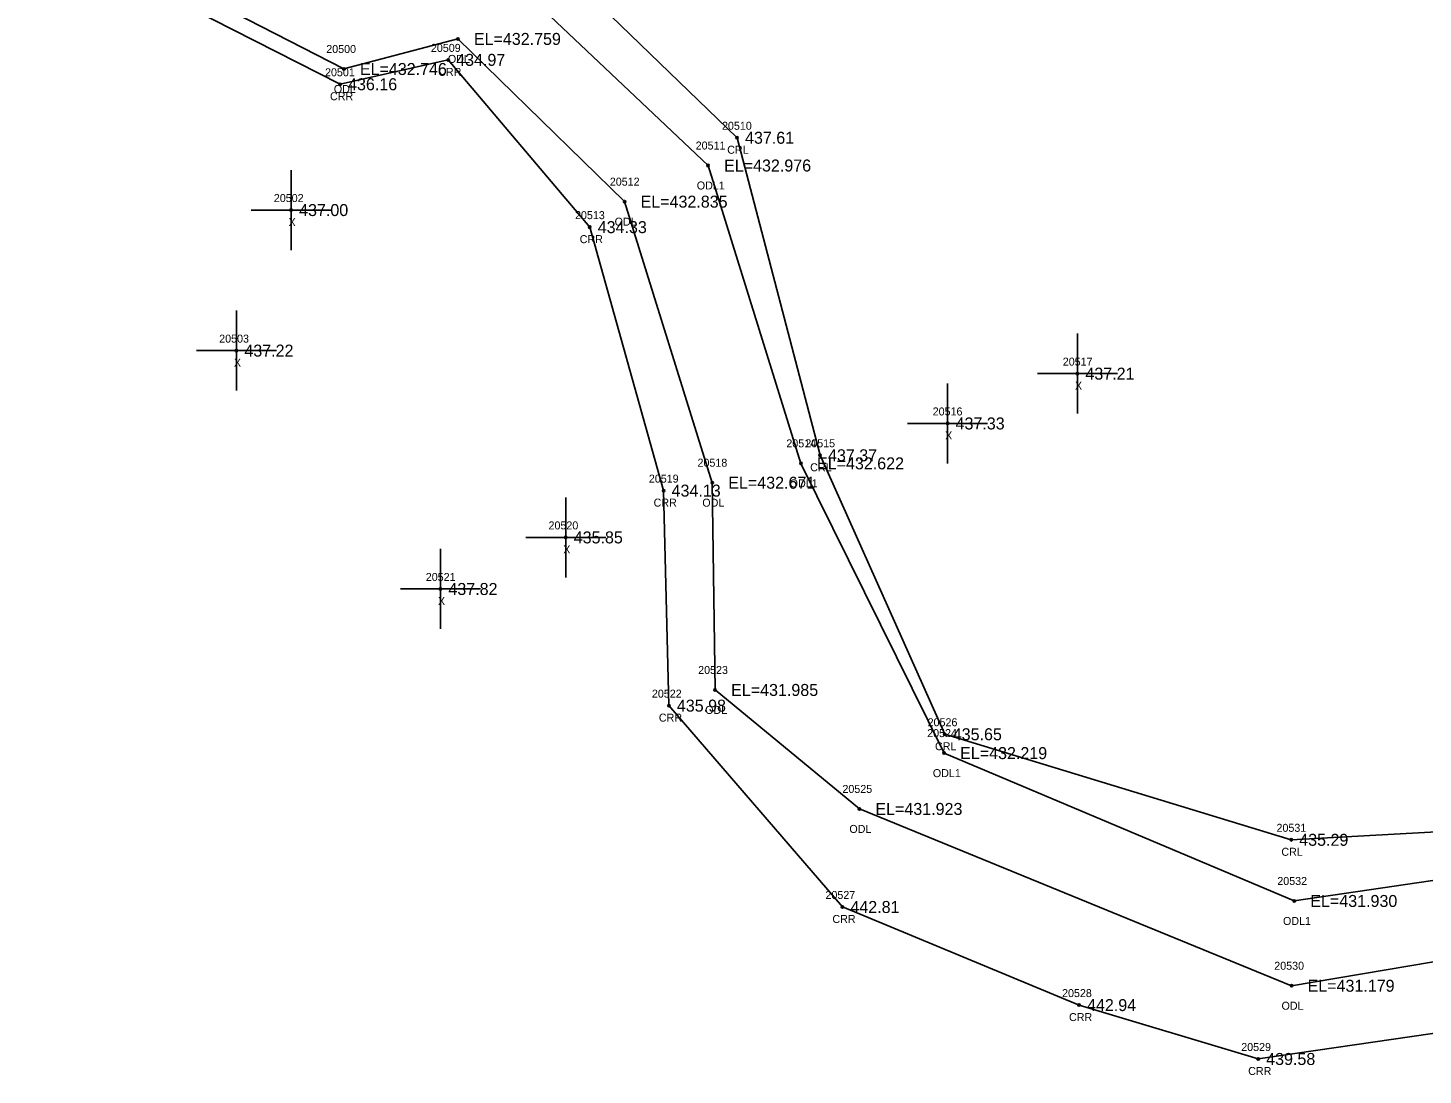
# Model space of a CAD drawing. Extents: x 1763022 to 1764007, y 824123 to 825394.
# Drawn here: x 1763608.9 to 1763783.3, y 824553.2 to 824684.2 of the extents above; entities that cross this region are included whole.
import ezdxf

# ---------------------------------------------------------------- set-up
doc = ezdxf.new("R2010")
doc.units = 0
for name, color, linetype in [('RD_EX_H2O', 7, 'Continuous'), ('RD_EX_H2O_txCode', 7, 'Continuous'), ('RD_EX_Misc', 7, 'Continuous'), ('RD_EX_Misc_txCode', 7, 'Continuous'), ('RD_EX_TX_H2O_ELEV', 7, 'Continuous'), ('RD_EX_TX_Misc_ELEV', 7, 'Continuous'), ('RD_SMD_Locator', 7, 'Continuous')]:
    doc.layers.add(name, color=color, linetype=linetype)

msp = doc.modelspace()

# ---------------------------------------------------------------- linework, layer by layer
at = {"layer": 'RD_EX_H2O'}
for points in [[(1763496.79, 824812.85), (1763505.69, 824806.42), (1763507.16, 824805.23), (1763521.58, 824789.49), (1763543.54, 824765.51), (1763572.14, 824752.09), (1763662.42, 824704.48), (1763697.56, 824670.47), (1763707.93, 824630.76), (1763723.52, 824595.87), (1763766.82, 824582.67), (1763818.29, 824585.49), (1763920.08, 824604.11)], [(1763494.44, 824810.56), (1763519.46, 824787), (1763539.48, 824759.37), (1763565.01, 824743.23), (1763659.79, 824699.35), (1763693.94, 824667), (1763705.55, 824629.75), (1763723.44, 824593.51), (1763767.2, 824575.02), (1763820.02, 824582.79), (1763920.83, 824600.99)], [(1763486.08, 824799.65), (1763514.15, 824779.95), (1763533.52, 824748.31), (1763547.12, 824731.03), (1763648.42, 824679.07), (1763662.67, 824682.83), (1763683.5, 824662.48), (1763694.46, 824627.33), (1763694.82, 824601.41), (1763712.85, 824586.53), (1763766.86, 824564.42), (1763816.87, 824572.85), (1763926.33, 824585.82)], [(1763485.59, 824798.12), (1763510.28, 824776.41), (1763530.73, 824746.57), (1763546.51, 824728.76), (1763647.95, 824677.16), (1763661.46, 824680.21), (1763679.15, 824659.29), (1763688.38, 824626.34), (1763689.04, 824599.45), (1763710.73, 824574.27), (1763740.3, 824562), (1763762.69, 824555.26), (1763820.3, 824563.65), (1763926.69, 824582.3)]]:
    msp.add_lwpolyline(points, dxfattribs=at)
at = {"layer": 'RD_EX_Misc'}
for p, q in [((1763641.83, 824656.43), (1763641.83, 824666.43)), ((1763636.83, 824661.43), (1763646.83, 824661.43)), ((1763634.99, 824638.85), (1763634.99, 824648.85)), ((1763740.1, 824635.97), (1763740.1, 824645.97)), ((1763629.99, 824643.85), (1763639.99, 824643.85)), ((1763735.1, 824640.97), (1763745.1, 824640.97)), ((1763723.87, 824629.74), (1763723.87, 824639.74)), ((1763718.87, 824634.74), (1763728.87, 824634.74)), ((1763676.15, 824615.49), (1763676.15, 824625.49)), ((1763671.15, 824620.49), (1763681.15, 824620.49)), ((1763660.49, 824609.04), (1763660.49, 824619.04)), ((1763655.49, 824614.04), (1763665.49, 824614.04))]:
    msp.add_line(p, q, dxfattribs=at)
at = {"layer": 'RD_SMD_Locator'}
for centre in [(1763662.67, 824682.83), (1763648.42, 824679.07), (1763661.46, 824680.21), (1763647.95, 824677.16), (1763697.56, 824670.47), (1763693.94, 824667), (1763641.83, 824661.43), (1763683.5, 824662.48), (1763679.15, 824659.29), (1763634.99, 824643.85), (1763740.1, 824640.97), (1763723.87, 824634.74), (1763705.55, 824629.75), (1763707.93, 824630.76), (1763688.38, 824626.34), (1763694.46, 824627.33), (1763676.15, 824620.49), (1763660.49, 824614.04), (1763694.82, 824601.41), (1763689.04, 824599.45), (1763723.52, 824595.87), (1763723.44, 824593.51), (1763712.85, 824586.53), (1763766.82, 824582.67), (1763710.73, 824574.27), (1763767.2, 824575.02), (1763766.86, 824564.42), (1763740.3, 824562), (1763762.69, 824555.26)]:
    msp.add_circle(centre, 0.15, dxfattribs=at)

# ---------------------------------------------------------------- texts
at = {"layer": 'RD_EX_H2O_txCode'}
for s, p in [('20509', (1763659.3, 824681.21)), ('20500', (1763646.22, 824681.07)), ('ODL', (1763661.42, 824679.83)), ('20501', (1763646.07, 824678.16)), ('CRR', (1763660.21, 824678.21)), ('ODL', (1763647.17, 824676.07)), ('CRR', (1763646.69, 824675.16)), ('20510', (1763695.68, 824671.47)), ('20511', (1763692.39, 824669)), ('CRL', (1763696.33, 824668.47)), ('20512', (1763681.66, 824664.48)), ('ODL1', (1763692.53, 824664)), ('20513', (1763677.31, 824660.29)), ('ODL', (1763682.26, 824659.48)), ('CRR', (1763677.9, 824657.29)), ('20514', (1763703.72, 824631.75)), ('20515', (1763706.09, 824631.76)), ('20518', (1763692.62, 824629.33)), ('20519', (1763686.54, 824627.34)), ('CRL', (1763706.7, 824628.76)), ('ODL1', (1763704.14, 824626.75)), ('CRR', (1763687.13, 824624.34)), ('ODL', (1763693.22, 824624.33)), ('20523', (1763692.7, 824603.41)), ('20522', (1763686.92, 824600.45)), ('CRR', (1763687.79, 824597.45)), ('ODL', (1763693.58, 824598.41)), ('20526', (1763721.38, 824596.87)), ('20524', (1763721.32, 824595.51)), ('CRL', (1763722.3, 824593.87)), ('ODL1', (1763722.03, 824590.51)), ('20525', (1763710.73, 824588.53)), ('ODL', (1763711.6, 824583.53)), ('20531', (1763764.98, 824583.67)), ('CRL', (1763765.59, 824580.67)), ('20532', (1763765.08, 824577.02)), ('20527', (1763708.61, 824575.27)), ('CRR', (1763709.48, 824572.27)), ('ODL1', (1763765.79, 824572.02)), ('20530', (1763764.7, 824566.42)), ('20528', (1763738.18, 824563)), ('ODL', (1763765.61, 824561.42)), ('CRR', (1763739.05, 824560)), ('20529', (1763760.57, 824556.26)), ('CRR', (1763761.44, 824553.26))]:
    msp.add_text(s, height=1, dxfattribs=at).set_placement(p)
at = {"layer": 'RD_EX_Misc_txCode'}
for s, p in [('20502', (1763639.67, 824662.43)), ('X', (1763641.51, 824659.43)), ('20503', (1763632.84, 824644.85)), ('X', (1763634.68, 824641.85)), ('20517', (1763738.27, 824641.97)), ('X', (1763739.79, 824638.97)), ('20516', (1763722.01, 824635.74)), ('X', (1763723.56, 824632.74)), ('20520', (1763674, 824621.49)), ('X', (1763675.84, 824618.49)), ('20521', (1763658.66, 824615.04)), ('X', (1763660.18, 824612.04))]:
    msp.add_text(s, height=1, dxfattribs=at).set_placement(p)
at = {"layer": 'RD_EX_TX_H2O_ELEV'}
for s, p in [('EL=432.759', (1763664.67, 824682.08)), ('434.97', (1763662.46, 824679.46)), ('EL=432.746', (1763650.42, 824678.32)), ('436.16', (1763648.95, 824676.41)), ('437.61', (1763698.56, 824669.72)), ('EL=432.976', (1763695.94, 824666.25)), ('EL=432.835', (1763685.5, 824661.73)), ('434.33', (1763680.15, 824658.54)), ('EL=432.622', (1763707.55, 824629)), ('437.37', (1763708.93, 824630.01)), ('EL=432.671', (1763696.46, 824626.58)), ('434.13', (1763689.38, 824625.59)), ('EL=431.985', (1763696.82, 824600.66)), ('435.98', (1763690.04, 824598.7)), ('435.65', (1763724.52, 824595.12)), ('EL=432.219', (1763725.44, 824592.76)), ('EL=431.923', (1763714.85, 824585.78)), ('435.29', (1763767.82, 824581.92)), ('EL=431.930', (1763769.2, 824574.27)), ('442.81', (1763711.73, 824573.52)), ('EL=431.179', (1763768.86, 824563.67)), ('442.94', (1763741.3, 824561.25)), ('439.58', (1763763.69, 824554.51))]:
    msp.add_text(s, height=1.5, dxfattribs=at).set_placement(p)
at = {"layer": 'RD_EX_TX_Misc_ELEV'}
for s, p in [('437.00', (1763642.83, 824660.68)), ('437.22', (1763635.99, 824643.1)), ('437.21', (1763741.1, 824640.22)), ('437.33', (1763724.87, 824633.99)), ('435.85', (1763677.15, 824619.74)), ('437.82', (1763661.49, 824613.29))]:
    msp.add_text(s, height=1.5, dxfattribs=at).set_placement(p)

doc.saveas('drawing.dxf')
